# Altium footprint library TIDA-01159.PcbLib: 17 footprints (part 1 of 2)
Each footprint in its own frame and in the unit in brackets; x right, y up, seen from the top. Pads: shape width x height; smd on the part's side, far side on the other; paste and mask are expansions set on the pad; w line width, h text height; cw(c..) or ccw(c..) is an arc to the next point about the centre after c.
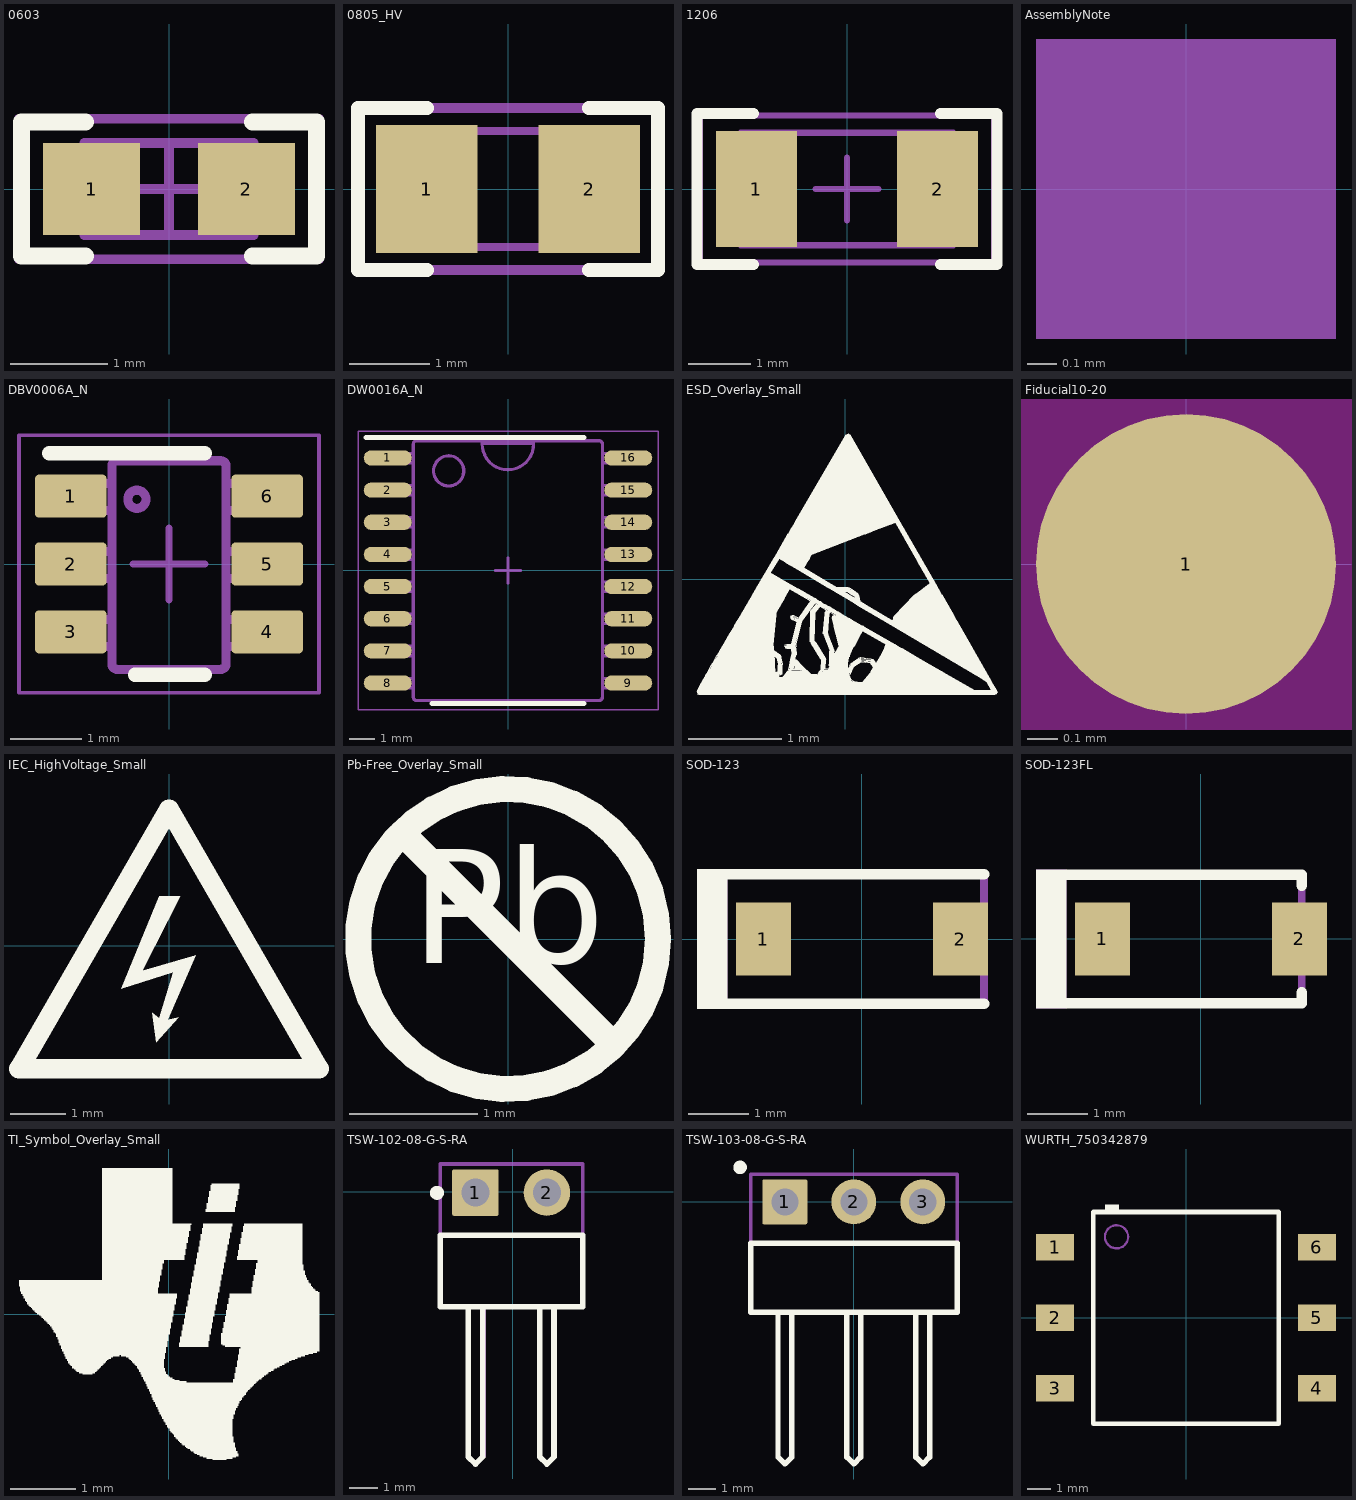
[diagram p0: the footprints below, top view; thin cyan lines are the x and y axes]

## 0603 [mm] "0603 from SM-752 data"
height 1
pads (2):
  rect 1x0.95 smd: 1(-0.8,0) 2(0.8,0)
Top Overlay:
  lines w0.178: -0.864,-0.691 -1.524,-0.691 -1.524,0.693 -0.864,0.693 ; 0.864,-0.691 1.524,-0.691 1.524,0.693 0.864,0.693
Mechanical 5:
  lines w0.1: -1.55,-0.725 -1.55,0.725 1.55,0.725 1.55,-0.725 -1.55,-0.725
  text ".Designator" at 0.559,0.406 h0.76
Mechanical 13:
  lines w0.1: -0.55,-0.475 -0.55,0.475 ; 0.55,-0.475 0.55,0.475 ; -0.875,-0.475 0.875,-0.475 0.875,0.475 -0.875,0.475 -0.875,-0.475
Mechanical 15:
  lines w0.1: -0.475,0 0.475,0 ; 0,-0.475 0,0.475 ; -1.55,-0.725 1.55,-0.725 1.55,0.725 -1.55,0.725 -1.55,-0.725
3D body: height 1, standoff 0, extent -0.874,-0.474 -0.551,0.474
3D body: height 1, standoff 0, extent -0.549,-0.474 0.549,0.474
3D body: height 1, standoff 0, extent 0.551,-0.474 0.874,0.474

## 0805_HV [mil] "0805 with 30mil clearance between pads"
height 57.09
pads (2):
  rect 50x63 smd: 1(-40,0) 2(40,0)
Top Overlay:
  lines w7: -40,-40 -74,-40 -74,0 -74,40 -40,40 ; 40,-40 74,-40 74,0 74,40 40,40
Mechanical 5:
  lines w5: -74,-40 74,-40 74,40 -74,40 -74,-40
  text ".Designator" at 20,15 h30
Mechanical 13:
  lines w3.94: -25.59,-28.54 -25.59,28.54 ; 25.59,-28.54 25.59,28.54 ; -43.31,-28.54 43.31,-28.54 43.31,28.54 -43.31,28.54 -43.31,-28.54
3D body: height 57.09, standoff 0, extent -43.29,-28.52 -25.61,28.52
3D body: height 57.09, standoff 0, extent -25.57,-28.52 25.57,28.52
3D body: height 57.09, standoff 0, extent 25.61,-28.52 43.29,28.52

## 1206 [mm] "1206 from SM-752 data"
height 1.35
pads (2):
  rect 1.3x1.85 smd: 1(-1.45,0) 2(1.45,0)
Top Overlay:
  lines w0.178: -1.5,-1.21 -2.4,-1.21 -2.4,1.21 -1.5,1.21 ; 1.5,-1.21 2.4,-1.21 2.4,1.21 1.5,1.21
Mechanical 5:
  lines w0.1: -1.7,-0.9 -1.7,0.9 1.7,0.9 1.7,-0.9 -1.7,-0.9
  text ".Designator" at 0.61,0.381 h0.76
Mechanical 13:
  lines w0.1: -1.2,-0.9 -1.2,0.9 ; 1.2,-0.9 1.2,0.9 ; -1.7,-0.9 -1.7,0.9 1.7,0.9 1.7,-0.9 -1.7,-0.9
Mechanical 15:
  lines w0.1: -0.5,0 0.5,0 ; 0,-0.5 0,0.5 ; -2.35,-1.175 -2.35,1.175 2.35,1.175 2.35,-1.175 -2.35,-1.175
3D body: height 1.35, standoff 0, extent 1.201,-0.899 1.699,0.899
3D body: height 1.35, standoff 0, extent -1.199,-0.899 1.199,0.899
3D body: height 1.35, standoff 0, extent -1.699,-0.899 -1.201,0.899

## AssemblyNote [mm] "Assembly Note"
Mechanical 5:
  rectangle: -0.508,-0.508 0.508,0.508
  text ".Comment" at 1.143,-0.508 h1.02
  text ".Designator" at -4.191,-0.508 h1.02

## DBV0006A_N [mm] "SOT23, 6-Leads, Body 2.9x1.6mm, Pitch 0.95mm, Lead Span 2.8mm, IPC Medium Density"
height 1.45
pads (6):
  rrect17% 1x0.6 smd: 1(-1.375,0.95) 2(-1.375,0) 3(-1.375,-0.95) 4(1.375,-0.95) 5(1.375,0) 6(1.375,0.95)
Top Overlay:
  lines w0.2: -1.675,1.55 0.5,1.55 ; -0.475,-1.55 0.5,-1.55
Mechanical 5:
  lines w0.127: 0.724,-1.475 ccw(c0.723,-1.399) 0.8,-1.399 0.8,1.37 ccw(c0.723,1.37) 0.724,1.446 ; 0.723,-1.475 0.724,-1.475 ; 0.723,-1.475 -0.724,-1.475 -0.725,-1.475 cw(c-0.724,-1.399) -0.801,-1.399 -0.801,1.37 cw(c-0.724,1.37) -0.725,1.446 -0.724,1.446 0.723,1.446 ; 0.723,1.446 0.724,1.446 ; -1.423,-1.154 -1.206,-1.154 -1.113,-1.154 -1.081,-1.154 -0.828,-1.154 -0.801,-1.154 -0.801,-0.78 -0.828,-0.78 -1.081,-0.78 -1.113,-0.78 -1.206,-0.78 -1.423,-0.78 -1.423,-1.154 ; -1.423,-0.202 -1.206,-0.202 -1.113,-0.202 -1.081,-0.202 -0.828,-0.202 -0.801,-0.202 -0.801,0.173 -0.828,0.173 -1.081,0.173 -1.113,0.173 -1.206,0.173 -1.423,0.173 -1.423,-0.202 ; -1.423,0.751 -1.206,0.751 -1.113,0.751 -1.081,0.751 -0.828,0.751 -0.801,0.751 -0.801,1.125 -0.828,1.125 -1.081,1.125 -1.113,1.125 -1.206,1.125 -1.423,1.125 -1.423,0.751 ; -0.577,0.906 cw(c-0.45,0.906) -0.323,0.906 cw(c-0.45,0.906) -0.577,0.906 ; 0.8,-1.154 0.827,-1.154 1.08,-1.154 1.112,-1.154 1.205,-1.154 1.422,-1.154 1.422,-0.78 1.205,-0.78 1.112,-0.78 1.08,-0.78 0.827,-0.78 0.8,-0.78 0.8,-1.154 ; 0.8,-0.202 0.827,-0.202 1.08,-0.202 1.112,-0.202 1.205,-0.202 1.422,-0.202 1.422,0.173 1.205,0.173 1.112,0.173 1.08,0.173 0.827,0.173 0.8,0.173 0.8,-0.202 ; 0.8,0.751 0.827,0.751 1.08,0.751 1.112,0.751 1.205,0.751 1.422,0.751 1.422,1.125 1.205,1.125 1.112,1.125 1.08,1.125 0.827,1.125 0.8,1.125 0.8,0.751
  text ".Designator" at -0.66,1.778 h0.76
Mechanical 15:
  lines w0.05: -2.1,-1.8 2.1,-1.8 2.1,1.8 -2.1,1.8 -2.1,-1.8
  lines w0.1: -0.5,0 0.5,0 ; 0,-0.5 0,0.5
3D body: height 1.12, standoff 0, extent -1.422,-1.46 1.423,1.461

## DW0016A_N [mm] "SOIC, 16-Leads, Body 10.3x7.5mm, Pitch 1.27mm, IPC Medium Density"
height 2.64
pads (16):
  oval 1.9x0.6 smd: 1(-4.75,4.445) 2(-4.75,3.175) 3(-4.75,1.905) 4(-4.75,0.635) 5(-4.75,-0.635) 6(-4.75,-1.905) 7(-4.75,-3.175) 8(-4.75,-4.445) 9(4.75,-4.445) 10(4.75,-3.175) 11(4.75,-1.905) 12(4.75,-0.635) 13(4.75,0.635) 14(4.75,1.905) 15(4.75,3.175) 16(4.75,4.445)
Top Overlay:
  lines w0.2: -5.6,5.25 3,5.25 ; -3,-5.25 3,-5.25
Mechanical 5:
  drawing of 193 lines, arcs and shapes, not listed
  text ".Designator" at 0.508,-0.508 h0.76
Mechanical 15:
  lines w0.05: -5.925,-5.5 5.925,-5.5 5.925,5.5 -5.925,5.5 -5.925,-5.5
  lines w0.1: -0.5,0 0.5,0 ; 0,-0.5 0,0.5
3D body: height 2.54, standoff 0, extent -5.143,-5.131 5.144,5.131

## ESD_Overlay_Small [mm]
height 0.33
Top Overlay:
  drawing of 901 lines, arcs and shapes, not listed

## Fiducial10-20 [mm]
pads (1):
  round 1 smd mask+0.5: 1(0,0)
Top Layer keep-out:
  circle w1.178: c0,0 r0.5

## IEC_HighVoltage_Small [mm]
height 0.33
Top Overlay:
  region: -0.178,0.889 0.203,0.889 -0.483,-0.457 0.483,-0.178 -0.025,-1.346 0.178,-1.295 -0.229,-1.753 -0.305,-1.219 -0.178,-1.321 0.076,-0.483 -0.864,-0.787
  lines w0.356: -2.718,-2.235 2.718,-2.235 0,2.472 -2.718,-2.235

## Pb-Free_Overlay_Small [mm]
Top Overlay:
  circle w0.203: c0,0 r1.168
  lines w0.203: -0.826,0.826 0.826,-0.826
  text "Pb" at -0.752,-0.48 h1.52

## SOD-123 [mm] "On Semi recommended land pattern"
height 1.35
pads (2):
  rect 0.915x1.22 smd: 1(-1.637,0) 2(1.637,0)
Top Overlay:
  rectangle: -2.743,-1.168 -2.235,1.168
  lines w0.178: -2.413,-1.079 2.032,-1.079 ; -2.413,1.079 2.032,1.079
Mechanical 5:
  rectangle: -2.743,-1.168 -2.235,1.168
  lines w0.127: -2.413,-1.079 2.032,-1.079 2.032,1.079 -2.413,1.079
  text ".Designator" at -0.838,-0.381 h0.76
3D body: height 1.35, standoff 0, extent -1.932,-0.9 1.932,0.9

## SOD-123FL [mm] "Copied from SOD-123"
height 0.991
pads (2):
  rect 0.915x1.22 smd: 1(-1.637,0) 2(1.637,0)
Top Overlay:
  rectangle: -2.743,-1.156 -2.235,1.156
  lines w0.178: -2.438,-1.067 1.676,-1.067 1.676,-0.889 ; -2.438,1.067 1.676,1.067 1.676,0.889
Mechanical 5:
  rectangle: -2.743,-1.156 -2.235,1.156
  lines w0.127: -2.438,-1.067 1.676,-1.067 1.676,1.067 -2.438,1.067
  text ".Designator" at -0.66,-0.356 h0.76
3D body: height 1, standoff 0, extent -1.9,-0.9 1.9,0.9

## TI_Symbol_Overlay_Small [mm]
Top Overlay:
  drawing of 3 lines, arcs and shapes, not listed

## TSW-102-08-G-S-RA [mm] "Samtec Right Angle Header"
height 2.794
pads (2):
  rrect6% 1.65x1.65 hole 1: 1(-1.321,-0.025)
  round 1.65 hole 1: 2(1.219,-0.025)
Top Overlay:
  circle w0.25: c-2.691,-0.035 r0.125
  lines w0.2: -1.575,-4.089 -1.575,-9.423 -1.321,-9.677 -1.067,-9.423 -1.067,-4.089 ; 0.965,-4.089 0.965,-9.423 1.219,-9.677 1.473,-9.423 1.473,-4.089 ; -2.571,-4.089 2.489,-4.089 2.489,-1.549 -2.571,-1.549 -2.571,-4.089
Mechanical 5:
  lines w0.127: -1.575,-4.089 -1.575,-9.423 -1.321,-9.677 -1.067,-9.423 ; -1.016,-9.398 -1.016,-4.064 ; 0.965,-4.089 0.965,-9.423 1.219,-9.677 1.473,-9.423 1.473,-4.089 ; 1.524,-9.398 1.524,-4.064 ; -2.571,-4.089 -2.571,0.991 2.489,0.991 2.489,-4.089 -2.571,-4.089
  text ".Designator" at -0.94,-2.819 h0.76
3D body: height 3.05, standoff -2.29, extent -2.591,-9.931 2.489,0.293

## TSW-103-08-G-S-RA [mm] "Samtec Right Angle Header"
height 2.794
pads (3):
  rrect6% 1.65x1.65 hole 1: 1(-2.54,0)
  round 1.65 hole 1: 2(0,0) 3(2.54,0)
Top Overlay:
  circle w0.25: c-4.189,1.27 r0.125
  lines w0.2: -2.794,-4.064 -2.794,-9.398 -2.54,-9.652 -2.286,-9.398 -2.286,-4.064 ; -0.254,-4.064 -0.254,-9.398 0,-9.652 0.254,-9.398 0.254,-4.064 ; 2.286,-4.064 2.286,-9.398 2.54,-9.652 2.794,-9.398 2.794,-4.064 ; -3.79,-4.064 3.81,-4.064 3.81,-1.524 -3.79,-1.524 -3.79,-4.064
Mechanical 5:
  lines w0.127: -2.794,-4.064 -2.794,-9.398 -2.54,-9.652 -2.286,-9.398 -2.286,-4.064 ; -0.254,-4.064 -0.254,-9.398 0,-9.652 0.254,-9.398 ; 2.286,-4.064 2.286,-9.398 2.54,-9.652 2.794,-9.398 ; 0.254,-9.398 0.254,-4.064 0.254,-9.398 ; 2.794,-9.398 2.794,-4.064 2.794,-9.398 ; -3.79,-4.064 -3.79,1.016 3.81,1.016 3.81,-4.064 -3.79,-4.064
  text ".Designator" at -0.457,-2.845 h0.76
3D body: height 3.05, standoff -2.29, extent -3.81,-9.906 3.81,0.318

## WURTH_750342879 [mm] "SMD, 6-Leads, Body 9.14x8mm, Pitch 3.05mm"
height 7.62
pads (6):
  rect 1.649x1.14 smd: 1(-5.655,3.05) 2(-5.655,0) 3(-5.655,-3.05) 4(5.655,-3.05) 5(5.655,0) 6(5.655,3.05)
Top Overlay:
  rectangle: -3.5,4.57 -2.9,4.9
  lines w0.2: -4,-4.57 -4,4.57 4,4.57 4,-4.57 -4,-4.57
Mechanical 5:
  circle w0.1: c-3,3.5 r0.5
  lines w0.1: -4,-4.57 4,-4.57 4,4.57 -4,4.57 -4,-4.57
  text ".Designator" at 0.838,1.219 h1.02
3D body: height 5, standoff 0, extent -4,-4.57 4,4.57
3D body: height 7.82, standoff 6.5, extent -4,-4.57 4,4.57
3D body: height 6.5, standoff 5, extent -2,-4.57 2,4.57
3D body: height 7.83, standoff 7.8, extent -3.509,2.991 -2.491,4.009
3D body: height 0.8, standoff 0, extent 3.849,2.75 6.35,3.35
3D body: height 0.8, standoff 0, extent 3.849,-0.3 6.35,0.3
3D body: height 0.8, standoff 0, extent 3.849,-3.35 6.35,-2.75
3D body: height 0.8, standoff 0, extent -6.35,-3.35 -3.849,-2.75
3D body: height 0.8, standoff 0, extent -6.35,-0.3 -3.849,0.3
3D body: height 0.8, standoff 0, extent -6.35,2.75 -3.849,3.35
